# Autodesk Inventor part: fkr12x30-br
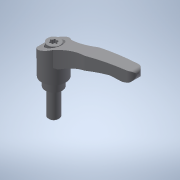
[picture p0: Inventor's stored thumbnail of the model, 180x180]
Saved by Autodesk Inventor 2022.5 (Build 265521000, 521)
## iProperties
Created: 2017-09
Part Number: fkr12x30-br
Material: 一般
Document SubType Name: Modeling
Designer: imaocorp
Density: 1 g/cm^3
Appearance: 既定
Author: imaocorp
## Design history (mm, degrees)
node "fkr12x30-br.x_t1"
node "fkr12x30-br"
node "Base1"
